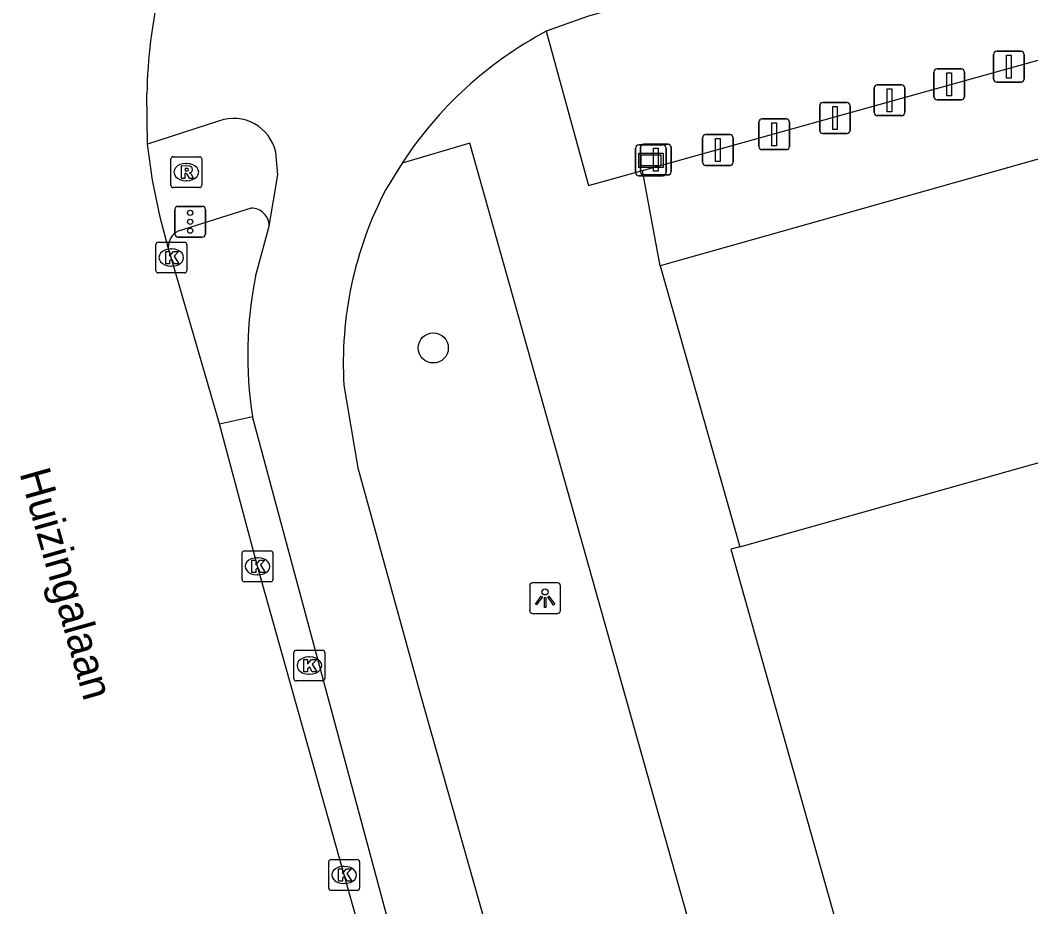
# Model space of a CAD drawing. Extents: x 159689 to 160786, y 387323 to 388339.
# Drawn here: x 159688.73 to 159721.53, y 388136.03 to 388164.81 of the extents above; entities that cross this region are included whole.
import ezdxf

# ---------------------------------------------------------------- set-up
doc = ezdxf.new("R2010")
doc.units = 0
for name, color, linetype in [('IMGEO_Afsluitpaal', 7, 'Continuous'), ('IMGEO_Boom', 7, 'Continuous'), ('IMGEO_Fietspad_gesloten', 7, 'Continuous'), ('IMGEO_Kolk', 7, 'Continuous'), ('IMGEO_Lichtpunt', 7, 'Continuous'), ('IMGEO_Openbare_ruimte_label', 7, 'Continuous'), ('IMGEO_Pand', 7, 'Continuous'), ('IMGEO_Rijbaan_regionaal_gesloten', 7, 'Continuous'), ('IMGEO_Rioolput', 7, 'Continuous'), ('IMGEO_Verkeerseiland_groen', 7, 'Continuous'), ('IMGEO_Verkeersregelinstallatiepaal', 7, 'Continuous'), ('IMGEO_Verklikker', 7, 'Continuous'), ('IMGEO_Voetpad_open', 7, 'Continuous')]:
    doc.layers.add(name, color=color, linetype=linetype)

msp = doc.modelspace()

# ---------------------------------------------------------------- linework, layer by layer
at = {"layer": 'IMGEO_Afsluitpaal'}
for p, q in [((159720.32, 388162.901), (159720.32, 388163.701)), ((159720.32, 388163.701), (159720.32, 388162.901)), ((159720.42, 388163.801), (159721.21, 388163.801)), ((159721.21, 388163.801), (159720.42, 388163.801)), ((159721.31, 388163.701), (159721.31, 388162.901)), ((159721.31, 388162.901), (159721.31, 388163.701)), ((159718.385, 388162.327), (159718.385, 388163.127)), ((159718.385, 388163.127), (159718.385, 388162.327)), ((159718.485, 388163.227), (159719.275, 388163.227)), ((159719.275, 388163.227), (159718.485, 388163.227)), ((159719.375, 388163.127), (159719.375, 388162.327)), ((159719.375, 388162.327), (159719.375, 388163.127)), ((159716.544, 388162.713), (159717.334, 388162.713)), ((159717.334, 388162.713), (159716.544, 388162.713)), ((159721.21, 388162.801), (159720.42, 388162.801)), ((159720.42, 388162.801), (159721.21, 388162.801)), ((159716.444, 388161.813), (159716.444, 388162.613)), ((159716.444, 388162.613), (159716.444, 388161.813)), ((159717.434, 388162.613), (159717.434, 388161.813)), ((159717.434, 388161.813), (159717.434, 388162.613)), ((159714.677, 388161.235), (159714.677, 388162.035)), ((159714.677, 388162.035), (159714.677, 388161.235)), ((159714.777, 388162.135), (159715.567, 388162.135)), ((159715.567, 388162.135), (159714.777, 388162.135)), ((159715.667, 388162.035), (159715.667, 388161.235)), ((159715.667, 388161.235), (159715.667, 388162.035)), ((159719.275, 388162.227), (159718.485, 388162.227)), ((159718.485, 388162.227), (159719.275, 388162.227)), ((159717.334, 388161.713), (159716.544, 388161.713)), ((159716.544, 388161.713), (159717.334, 388161.713)), ((159712.706, 388160.709), (159712.706, 388161.509)), ((159712.706, 388161.509), (159712.706, 388160.709)), ((159712.806, 388161.609), (159713.596, 388161.609)), ((159713.596, 388161.609), (159712.806, 388161.609)), ((159713.696, 388161.509), (159713.696, 388160.709)), ((159713.696, 388160.709), (159713.696, 388161.509)), ((159710.977, 388161.097), (159711.767, 388161.097)), ((159711.767, 388161.097), (159710.977, 388161.097)), ((159715.567, 388161.135), (159714.777, 388161.135)), ((159714.777, 388161.135), (159715.567, 388161.135)), ((159708.964, 388160.786), (159709.754, 388160.786)), ((159709.754, 388160.786), (159708.964, 388160.786)), ((159710.877, 388160.197), (159710.877, 388160.997)), ((159710.877, 388160.997), (159710.877, 388160.197)), ((159711.867, 388160.997), (159711.867, 388160.197)), ((159711.867, 388160.197), (159711.867, 388160.997)), ((159708.864, 388159.886), (159708.864, 388160.686)), ((159708.864, 388160.686), (159708.864, 388159.886)), ((159709.854, 388160.686), (159709.854, 388159.886)), ((159709.854, 388159.886), (159709.854, 388160.686)), ((159713.596, 388160.609), (159712.806, 388160.609)), ((159712.806, 388160.609), (159713.596, 388160.609)), ((159711.767, 388160.097), (159710.977, 388160.097)), ((159710.977, 388160.097), (159711.767, 388160.097)), ((159709.754, 388159.786), (159708.964, 388159.786)), ((159708.964, 388159.786), (159709.754, 388159.786))]:
    msp.add_line(p, q, dxfattribs=at)
for points in [[(159720.74, 388163.676), (159720.89, 388163.676), (159720.89, 388162.926), (159720.74, 388162.926), (159720.74, 388163.676)], [(159718.805, 388163.102), (159718.955, 388163.102), (159718.955, 388162.352), (159718.805, 388162.352), (159718.805, 388163.102)], [(159716.864, 388162.588), (159717.014, 388162.588), (159717.014, 388161.838), (159716.864, 388161.838), (159716.864, 388162.588)], [(159715.097, 388162.01), (159715.247, 388162.01), (159715.247, 388161.26), (159715.097, 388161.26), (159715.097, 388162.01)], [(159713.126, 388161.484), (159713.276, 388161.484), (159713.276, 388160.734), (159713.126, 388160.734), (159713.126, 388161.484)], [(159711.297, 388160.972), (159711.447, 388160.972), (159711.447, 388160.222), (159711.297, 388160.222), (159711.297, 388160.972)], [(159709.284, 388160.661), (159709.434, 388160.661), (159709.434, 388159.911), (159709.284, 388159.911), (159709.284, 388160.661)]]:
    msp.add_lwpolyline(points, dxfattribs=at)
for centre, start, end in [((159720.42, 388163.701), 90, 180), ((159720.42, 388163.701), 90, 180), ((159721.21, 388163.701), 0, 90), ((159721.21, 388163.701), 360, 90), ((159718.485, 388163.127), 90, 180), ((159718.485, 388163.127), 90, 180), ((159719.275, 388163.127), 0, 90), ((159719.275, 388163.127), 360, 90), ((159716.544, 388162.613), 90, 180), ((159716.544, 388162.613), 90, 180), ((159717.334, 388162.613), 0, 90), ((159717.334, 388162.613), 360, 90), ((159720.42, 388162.901), 180, 270), ((159720.42, 388162.901), 180, 270), ((159721.21, 388162.901), 270, 0), ((159721.21, 388162.901), 270, 0), ((159714.777, 388162.035), 90, 180), ((159714.777, 388162.035), 90, 180), ((159715.567, 388162.035), 0, 90), ((159715.567, 388162.035), 360, 90), ((159718.485, 388162.327), 180, 270), ((159718.485, 388162.327), 180, 270), ((159719.275, 388162.327), 270, 0), ((159719.275, 388162.327), 270, 0), ((159716.544, 388161.813), 180, 270), ((159716.544, 388161.813), 180, 270), ((159717.334, 388161.813), 270, 0), ((159717.334, 388161.813), 270, 0), ((159712.806, 388161.509), 90, 180), ((159712.806, 388161.509), 90, 180), ((159713.596, 388161.509), 0, 90), ((159713.596, 388161.509), 360, 90), ((159710.977, 388160.997), 90, 180), ((159710.977, 388160.997), 90, 180), ((159711.767, 388160.997), 0, 90), ((159711.767, 388160.997), 360, 90), ((159714.777, 388161.235), 180, 270), ((159714.777, 388161.235), 180, 270), ((159715.567, 388161.235), 270, 0), ((159715.567, 388161.235), 270, 0), ((159708.964, 388160.686), 90, 180), ((159708.964, 388160.686), 90, 180), ((159709.754, 388160.686), 0, 90), ((159709.754, 388160.686), 360, 90), ((159712.806, 388160.709), 180, 270), ((159712.806, 388160.709), 180, 270), ((159713.596, 388160.709), 270, 0), ((159713.596, 388160.709), 270, 0), ((159710.977, 388160.197), 180, 270), ((159710.977, 388160.197), 180, 270), ((159711.767, 388160.197), 270, 0), ((159711.767, 388160.197), 270, 0), ((159708.964, 388159.886), 180, 270), ((159708.964, 388159.886), 180, 270), ((159709.754, 388159.886), 270, 0), ((159709.754, 388159.886), 270, 0)]:
    msp.add_arc(centre, 0.1, start, end, dxfattribs=at)
at = {"layer": 'IMGEO_Boom'}
msp.add_circle((159702.136, 388154.171), 0.489, dxfattribs=at)
at = {"layer": 'IMGEO_Fietspad_gesloten'}
for points in [[(159723.633, 388169.719), (159721.106, 388168.977), (159707.145, 388164.927), (159705.804, 388164.452)], [(159695.195, 388161.544), (159692.861, 388160.79)], [(159696.81, 388158.125), (159697.09, 388159.791), (159697.023, 388160.532)], [(159701.126, 388160.169), (159700.596, 388159.313)], [(159696.37, 388156.492), (159696.81, 388158.125)], [(159699.238, 388152.96), (159699.688, 388150.278), (159701.735, 388142.864), (159713.692, 388100.589)], [(159714.922, 388085.647), (159713.8, 388089.138), (159708.235, 388108.71), (159701.005, 388134.325), (159696.271, 388151.945)]]:
    msp.add_lwpolyline(points, dxfattribs=at)
for centre, radius, start, end in [((159711.797, 388153.21), 12.74, 118.0621, 146.89), ((159695.658, 388160.223), 1.399, 12.7415, 109.3197), ((159711.369, 388153.689), 12.152, 152.431, 183.4374), ((159708.931, 388153.944), 12.817, 168.5329, 188.9726)]:
    msp.add_arc(centre, radius, start, end, dxfattribs=at)
at = {"layer": 'IMGEO_Kolk'}
for p, q in [((159693.135, 388156.679), (159693.135, 388157.531)), ((159693.21, 388157.605), (159694.062, 388157.605)), ((159694.136, 388157.531), (159694.136, 388156.679)), ((159693.623, 388157.385), (159693.648, 388157.385)), ((159693.646, 388156.825), (159693.621, 388156.825)), ((159694.062, 388156.605), (159693.21, 388156.605)), ((159696.008, 388147.58), (159696.86, 388147.58)), ((159695.933, 388146.654), (159695.933, 388147.506)), ((159696.421, 388147.36), (159696.446, 388147.36)), ((159696.934, 388147.506), (159696.934, 388146.654)), ((159696.444, 388146.8), (159696.419, 388146.8)), ((159696.86, 388146.58), (159696.008, 388146.58)), ((159697.69, 388144.357), (159698.542, 388144.357)), ((159697.615, 388143.431), (159697.615, 388144.283)), ((159698.103, 388144.137), (159698.128, 388144.137)), ((159698.616, 388144.283), (159698.616, 388143.431)), ((159698.542, 388143.357), (159697.69, 388143.357)), ((159698.126, 388143.577), (159698.101, 388143.577)), ((159698.745, 388136.633), (159698.745, 388137.485)), ((159698.82, 388137.559), (159699.672, 388137.559)), ((159699.746, 388137.485), (159699.746, 388136.633)), ((159699.233, 388137.339), (159699.258, 388137.339)), ((159699.256, 388136.779), (159699.231, 388136.779)), ((159699.672, 388136.559), (159698.82, 388136.559))]:
    msp.add_line(p, q, dxfattribs=at)
for points in [[(159693.135, 388156.679), (159693.135, 388157.531)], [(159693.21, 388157.605), (159694.062, 388157.605)], [(159694.136, 388157.531), (159694.136, 388156.679)], [(159693.456, 388157.305), (159693.579, 388157.305), (159693.579, 388157.154), (159693.709, 388157.305), (159693.873, 388157.305), (159693.727, 388157.154), (159693.88, 388156.905), (159693.728, 388156.905), (159693.643, 388157.069), (159693.579, 388157.002), (159693.579, 388156.905), (159693.456, 388156.905), (159693.456, 388157.305)], [(159694.062, 388156.605), (159693.21, 388156.605)], [(159696.008, 388147.58), (159696.86, 388147.58)], [(159695.933, 388146.654), (159695.933, 388147.506)], [(159696.254, 388147.28), (159696.377, 388147.28), (159696.377, 388147.129), (159696.507, 388147.28), (159696.671, 388147.28), (159696.525, 388147.129), (159696.678, 388146.88), (159696.526, 388146.88), (159696.441, 388147.044), (159696.377, 388146.977), (159696.377, 388146.88), (159696.254, 388146.88), (159696.254, 388147.28)], [(159696.934, 388147.506), (159696.934, 388146.654)], [(159696.86, 388146.58), (159696.008, 388146.58)], [(159697.69, 388144.357), (159698.542, 388144.357)], [(159697.615, 388143.431), (159697.615, 388144.283)], [(159697.936, 388144.057), (159698.059, 388144.057), (159698.059, 388143.906), (159698.189, 388144.057), (159698.353, 388144.057), (159698.207, 388143.906), (159698.36, 388143.657), (159698.208, 388143.657), (159698.123, 388143.821), (159698.059, 388143.754), (159698.059, 388143.657), (159697.936, 388143.657), (159697.936, 388144.057)], [(159698.616, 388144.283), (159698.616, 388143.431)], [(159698.542, 388143.357), (159697.69, 388143.357)], [(159698.745, 388136.633), (159698.745, 388137.485)], [(159698.82, 388137.559), (159699.672, 388137.559)], [(159699.746, 388137.485), (159699.746, 388136.633)], [(159699.066, 388137.259), (159699.189, 388137.259), (159699.189, 388137.108), (159699.319, 388137.259), (159699.483, 388137.259), (159699.337, 388137.108), (159699.49, 388136.859), (159699.338, 388136.859), (159699.253, 388137.023), (159699.189, 388136.956), (159699.189, 388136.859), (159699.066, 388136.859), (159699.066, 388137.259)], [(159699.672, 388136.559), (159698.82, 388136.559)]]:
    msp.add_lwpolyline(points, dxfattribs=at)
for centre, start, end in [((159693.212, 388157.529), 91.552, 178.448), ((159693.212, 388157.529), 91.552, 178.448), ((159694.06, 388157.529), 1.552, 88.448), ((159694.06, 388157.529), 1.552, 88.448), ((159693.212, 388156.681), 181.552, 268.448), ((159693.212, 388156.681), 181.552, 268.448), ((159694.06, 388156.681), 271.552, 358.448), ((159694.06, 388156.681), 271.552, 358.448), ((159696.01, 388147.504), 91.552, 178.448), ((159696.01, 388147.504), 91.552, 178.448), ((159696.858, 388147.504), 1.552, 88.448), ((159696.858, 388147.504), 1.552, 88.448), ((159696.01, 388146.656), 181.552, 268.448), ((159696.01, 388146.656), 181.552, 268.448), ((159696.858, 388146.656), 271.552, 358.448), ((159696.858, 388146.656), 271.552, 358.448), ((159697.692, 388144.281), 91.552, 178.448), ((159697.692, 388144.281), 91.552, 178.448), ((159698.54, 388144.281), 1.552, 88.448), ((159698.54, 388144.281), 1.552, 88.448), ((159697.692, 388143.433), 181.552, 268.448), ((159697.692, 388143.433), 181.552, 268.448), ((159698.54, 388143.433), 271.552, 358.448), ((159698.54, 388143.433), 271.552, 358.448), ((159698.822, 388137.483), 91.552, 178.448), ((159698.822, 388137.483), 91.552, 178.448), ((159699.67, 388137.483), 1.552, 88.448), ((159699.67, 388137.483), 1.552, 88.448), ((159698.822, 388136.635), 181.552, 268.448), ((159698.822, 388136.635), 181.552, 268.448), ((159699.67, 388136.635), 271.552, 358.448), ((159699.67, 388136.635), 271.552, 358.448)]:
    msp.add_arc(centre, 0.0765, start, end, dxfattribs=at)
for centre, major_axis, ratio, start_param, end_param in [((159693.622, 388157.105), (-0.387, 0.002), 0.722429, 4.712389, 7.853982), ((159693.647, 388157.105), (-0.39, 0.002), 0.717154, 1.570796, 4.712389), ((159696.42, 388147.08), (-0.387, 0.002), 0.722429, 4.712389, 7.853982), ((159696.445, 388147.08), (-0.39, 0.002), 0.717154, 1.570796, 4.712389), ((159698.102, 388143.857), (-0.387, 0.002), 0.722429, 4.712389, 7.853982), ((159698.127, 388143.857), (-0.39, 0.002), 0.717154, 1.570796, 4.712389), ((159699.232, 388137.059), (-0.387, 0.002), 0.722429, 4.712389, 7.853982), ((159699.257, 388137.059), (-0.39, 0.002), 0.717154, 1.570796, 4.712389)]:
    msp.add_ellipse(centre, major_axis=major_axis, ratio=ratio, start_param=start_param, end_param=end_param, dxfattribs=at)
at = {"layer": 'IMGEO_Lichtpunt'}
for p, q in [((159705.265, 388146.451), (159705.265, 388145.644)), ((159705.265, 388146.451), (159705.265, 388145.644)), ((159706.167, 388146.546), (159705.359, 388146.546)), ((159706.167, 388146.546), (159705.359, 388146.546)), ((159706.261, 388145.644), (159706.261, 388146.451)), ((159706.261, 388145.644), (159706.261, 388146.451)), ((159705.359, 388145.55), (159706.167, 388145.55)), ((159705.359, 388145.55), (159706.167, 388145.55))]:
    msp.add_line(p, q, dxfattribs=at)
for points in [[(159705.639, 388146.115), (159705.678, 388146.087), (159705.49, 388145.825), (159705.452, 388145.852), (159705.639, 388146.115)], [(159705.741, 388146.067), (159705.788, 388146.067), (159705.788, 388145.745), (159705.741, 388145.745), (159705.741, 388146.067)], [(159705.851, 388146.087), (159705.889, 388146.114), (159706.076, 388145.852), (159706.037, 388145.824), (159705.851, 388146.087)]]:
    msp.add_lwpolyline(points, dxfattribs=at)
msp.add_circle((159705.764, 388146.249), 0.0994, dxfattribs=at)
for centre, start, end in [((159705.359, 388146.451), 90, 180), ((159705.359, 388146.451), 90, 180), ((159706.167, 388146.451), 0, 90), ((159706.167, 388146.451), 0, 90), ((159705.359, 388145.644), 180, 270), ((159705.359, 388145.644), 180, 270), ((159706.167, 388145.644), 270, 0), ((159706.167, 388145.644), 270, 360)]:
    msp.add_arc(centre, 0.0946, start, end, dxfattribs=at)
at = {"layer": 'IMGEO_Pand'}
for points in [[(159712.08, 388147.715), (159734.959, 388154.16), (159735.05, 388153.839), (159739.21, 388155.023), (159739.248, 388154.887), (159739.302, 388154.694), (159763.357, 388161.491), (159763.459, 388161.519)], [(159712.08, 388147.715), (159711.789, 388147.633), (159723.951, 388104.478)]]:
    msp.add_lwpolyline(points, dxfattribs=at)
at = {"layer": 'IMGEO_Rijbaan_regionaal_gesloten'}
for points in [[(159692.861, 388160.79), (159692.843, 388162.429)], [(159693.538, 388157.435), (159693.27, 388158.421), (159693.025, 388159.619), (159692.861, 388160.79)], [(159695.201, 388151.706), (159693.636, 388157.105), (159693.538, 388157.435)], [(159713.105, 388087.616), (159712.776, 388088.821), (159709.976, 388098.854), (159707.423, 388107.93), (159704.613, 388117.962), (159702.063, 388127.028), (159699.246, 388137.059), (159696.434, 388147.08), (159695.201, 388151.706)]]:
    msp.add_lwpolyline(points, dxfattribs=at)
msp.add_arc((159708.554, 388162.193), 15.712, 166.5996, 179.1379, dxfattribs=at)
at = {"layer": 'IMGEO_Rioolput'}
for p, q in [((159693.698, 388160.379), (159694.55, 388160.379)), ((159693.623, 388159.453), (159693.623, 388160.305)), ((159694.111, 388160.159), (159694.136, 388160.159)), ((159694.624, 388160.305), (159694.624, 388159.453)), ((159694.55, 388159.379), (159693.698, 388159.379)), ((159694.134, 388159.599), (159694.109, 388159.599))]:
    msp.add_line(p, q, dxfattribs=at)
for points in [[(159693.698, 388160.379), (159694.55, 388160.379)], [(159693.623, 388159.453), (159693.623, 388160.305)], [(159694.212, 388160.077), (159693.96, 388160.079), (159693.96, 388159.679)], [(159694.624, 388160.305), (159694.624, 388159.453)], [(159693.96, 388159.679), (159694.084, 388159.679), (159694.084, 388159.841), (159694.095, 388159.841)], [(159694.138, 388159.998), (159694.084, 388159.998), (159694.084, 388159.917)], [(159694.084, 388159.917), (159694.136, 388159.917)], [(159694.142, 388159.812), (159694.213, 388159.679), (159694.353, 388159.679), (159694.288, 388159.805)], [(159694.55, 388159.379), (159693.698, 388159.379)]]:
    msp.add_lwpolyline(points, dxfattribs=at)
for centre, radius, start, end in [((159693.7, 388160.303), 0.0765, 91.552, 178.448), ((159693.7, 388160.303), 0.0765, 91.552, 178.448), ((159694.548, 388160.303), 0.0765, 1.552, 88.448), ((159694.548, 388160.303), 0.0765, 1.552, 88.448), ((159694.211, 388159.967), 0.109, 350.3612, 89.416), ((159694.094, 388159.788), 0.0533, 26.0293, 88.6989), ((159694.12, 388160.106), 0.19, 274.7715, 282.9687), ((159694.144, 388159.902), 0.0964, 77.0061, 93.1865), ((159694.158, 388159.959), 0.0378, 276.6634, 79.6772), ((159694.209, 388159.967), 0.112, 277.5842, 350.9817), ((159694.193, 388159.752), 0.108, 29.5134, 73.7905), ((159693.7, 388159.455), 0.0765, 181.552, 268.448), ((159693.7, 388159.455), 0.0765, 181.552, 268.448), ((159694.548, 388159.455), 0.0765, 271.552, 358.448), ((159694.548, 388159.455), 0.0765, 271.552, 358.448)]:
    msp.add_arc(centre, radius, start, end, dxfattribs=at)
for centre, major_axis, ratio, start_param, end_param in [((159694.11, 388159.879), (-0.387, 0.002), 0.722429, 4.712389, 7.853982), ((159694.135, 388159.879), (-0.39, 0.002), 0.717154, 1.570796, 4.712389)]:
    msp.add_ellipse(centre, major_axis=major_axis, ratio=ratio, start_param=start_param, end_param=end_param, dxfattribs=at)
at = {"layer": 'IMGEO_Verkeerseiland_groen'}
msp.add_lwpolyline([(159695.201, 388151.706), (159696.271, 388151.945)], dxfattribs=at)
at = {"layer": 'IMGEO_Verkeersregelinstallatiepaal'}
for p, q in [((159693.851, 388158.767), (159694.641, 388158.767)), ((159694.641, 388158.767), (159693.851, 388158.767)), ((159693.751, 388157.867), (159693.751, 388158.667)), ((159693.751, 388158.667), (159693.751, 388157.867)), ((159694.741, 388158.667), (159694.741, 388157.867)), ((159694.741, 388157.867), (159694.741, 388158.667)), ((159694.641, 388157.767), (159693.851, 388157.767)), ((159693.851, 388157.767), (159694.641, 388157.767))]:
    msp.add_line(p, q, dxfattribs=at)
for centre in [(159694.246, 388158.557), (159694.246, 388158.267), (159694.246, 388157.977)]:
    msp.add_circle(centre, 0.085, dxfattribs=at)
for centre, start, end in [((159693.851, 388158.667), 90, 180), ((159693.851, 388158.667), 90, 180), ((159694.641, 388158.667), 0, 90), ((159694.641, 388158.667), 360, 90), ((159693.851, 388157.867), 180, 270), ((159693.851, 388157.867), 180, 270), ((159694.641, 388157.867), 270, 0), ((159694.641, 388157.867), 270, 0)]:
    msp.add_arc(centre, 0.1, start, end, dxfattribs=at)
at = {"layer": 'IMGEO_Verklikker'}
for p, q in [((159708.803, 388160.762), (159709.593, 388160.762)), ((159709.593, 388160.762), (159708.803, 388160.762)), ((159708.703, 388159.862), (159708.703, 388160.662)), ((159708.703, 388160.662), (159708.703, 388159.862)), ((159709.693, 388160.662), (159709.693, 388159.862)), ((159709.693, 388159.862), (159709.693, 388160.662)), ((159709.593, 388159.762), (159708.803, 388159.762)), ((159708.803, 388159.762), (159709.593, 388159.762))]:
    msp.add_line(p, q, dxfattribs=at)
for points in [[(159708.804, 388160.494), (159709.592, 388160.494), (159709.592, 388160.03), (159708.804, 388160.03), (159708.804, 388160.494)], [(159708.869, 388160.429), (159708.869, 388160.095), (159709.527, 388160.095), (159709.527, 388160.429), (159708.869, 388160.429)]]:
    msp.add_lwpolyline(points, dxfattribs=at)
for centre, start, end in [((159708.803, 388160.662), 90, 180), ((159708.803, 388160.662), 90, 180), ((159709.593, 388160.662), 0, 90), ((159709.593, 388160.662), 360, 90), ((159708.803, 388159.862), 180, 270), ((159708.803, 388159.862), 180, 270), ((159709.593, 388159.862), 270, 0), ((159709.593, 388159.862), 270, 0)]:
    msp.add_arc(centre, 0.1, start, end, dxfattribs=at)
at = {"layer": 'IMGEO_Voetpad_open'}
for points in [[(159708.924, 388159.928), (159749.997, 388171.408)], [(159750.791, 388168.5), (159709.502, 388156.836)], [(159705.804, 388164.452), (159707.169, 388159.441), (159708.924, 388159.928)], [(159719.517, 388103.237), (159703.321, 388160.82), (159701.126, 388160.169)], [(159709.502, 388156.836), (159708.924, 388159.928)], [(159696.229, 388158.708), (159693.856, 388157.959)], [(159709.502, 388156.836), (159712.08, 388147.715)]]:
    msp.add_lwpolyline(points, dxfattribs=at)
for centre, radius, start, end in [((159696.238, 388158.136), 0.572, 358.8527, 90.9504), ((159694.111, 388157.446), 0.573, 116.428, 181.0674)]:
    msp.add_arc(centre, radius, start, end, dxfattribs=at)

# ---------------------------------------------------------------- texts
at = {"layer": 'IMGEO_Openbare_ruimte_label'}
msp.add_text('Huizingalaan', height=1, rotation=285.8431, dxfattribs=at).set_placement((159688.703, 388150.107))

doc.saveas('drawing.dxf')
